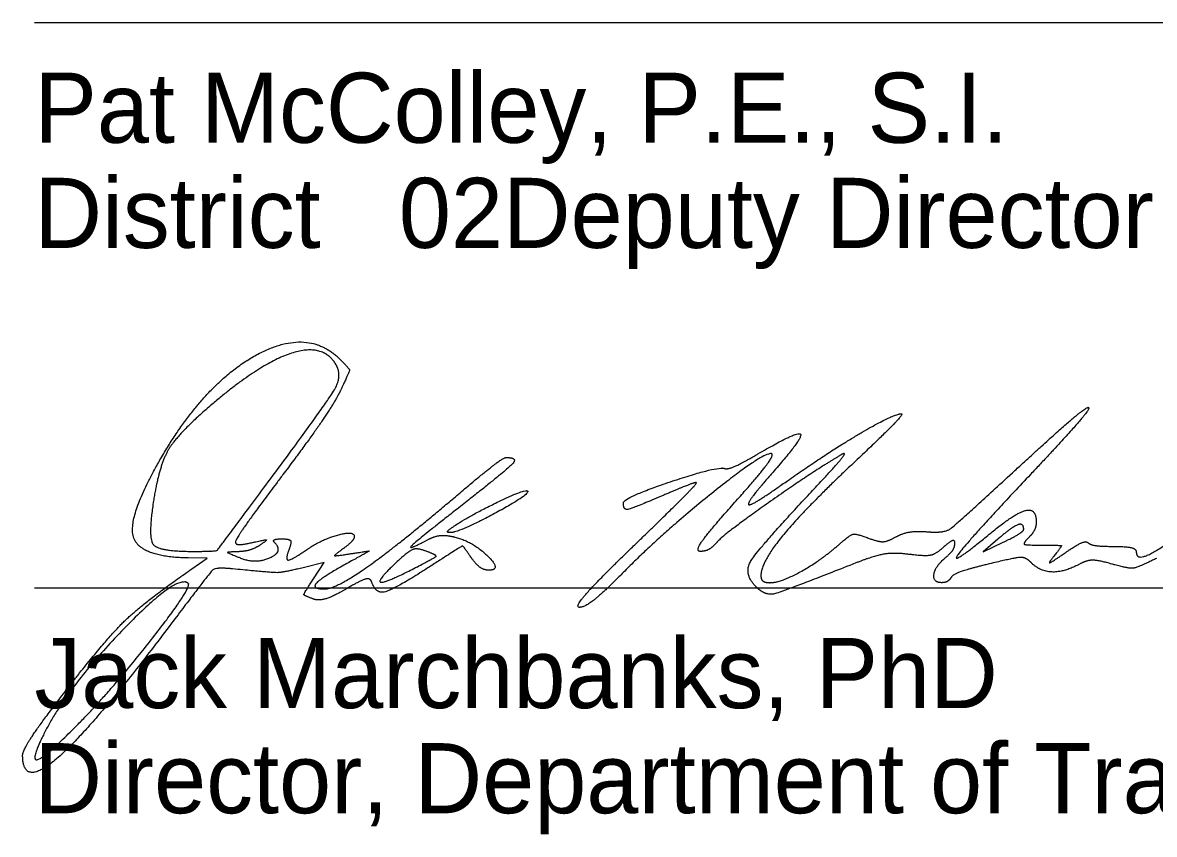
# Model space of a CAD drawing. Extents: x 0 to 34, y 0 to 22.
# Drawn here: x 24.504 to 26.766, y 7.305 to 8.926 of the extents above; entities that cross this region are included whole.
import ezdxf

# ---------------------------------------------------------------- set-up
doc = ezdxf.new("R2010")
doc.units = 0
doc.layers.add('SH_Data', color=7, linetype='Continuous')
doc.layers.add('SH_Text', color=7, linetype='Continuous')

msp = doc.modelspace()

# ---------------------------------------------------------------- linework, layer by layer
at = {"layer": 'SH_Data'}
for p, q in [((24.5279, 8.9262), (28.0279, 8.9262)), ((24.5279, 7.7968), (28.0279, 7.7968))]:
    msp.add_line(p, q, dxfattribs=at)
at = {"layer": 'SH_Text'}
for p, q in [((24.9902, 8.0019), (24.9902, 8.0019)), ((26.5045, 7.914), (26.5045, 7.914)), ((25.3555, 7.912), (25.3555, 7.912)), ((25.3107, 7.8703), (25.3107, 7.8703)), ((25.7273, 7.883), (25.7273, 7.883))]:
    msp.add_line(p, q, dxfattribs=at)
for points in [[(26.4527, 7.8943), (26.4232, 7.8687), (26.4638, 7.8884)], [(24.8425, 7.8349), (24.8732, 7.8561), (24.8354, 7.8568)], [(25.0855, 7.8151), (25.1067, 7.8474), (25.0649, 7.8373)]]:
    msp.add_lwpolyline(points, dxfattribs=at)
for points in [[(24.7789, 8.0526), (24.8651, 8.203), (25.0732, 8.319), (25.1389, 8.2534)], [(25.1299, 8.2442), (25.104, 8.2862), (24.9779, 8.245), (24.8825, 8.1634)], [(25.1389, 8.2534), (25.1577, 8.2346), (25.1577, 8.2295), (25.1394, 8.1911)], [(24.9902, 8.0019), (25.1115, 8.1653), (25.144, 8.2215), (25.1299, 8.2442)], [(25.1394, 8.1911), (25.1284, 8.1681), (25.0767, 8.0926), (25.0245, 8.0232)], [(24.8825, 8.1634), (24.8159, 8.1064), (24.7771, 8.0423), (24.766, 7.971)], [(26.0326, 8.0111), (26.1131, 8.0677), (26.2445, 8.1449), (26.2602, 8.1449)], [(26.2602, 8.1449), (26.265, 8.1449), (26.2237, 8.1023), (26.1684, 8.0502)], [(26.4869, 8.0315), (26.5619, 8.1006), (26.6279, 8.1572), (26.6336, 8.1573)], [(26.6336, 8.1573), (26.6394, 8.1574), (26.5873, 8.0972), (26.518, 8.0236)], [(25.9736, 8.0646), (26.0524, 8.1108), (26.0646, 8.0975), (26.0054, 8.0302)], [(24.8354, 7.8568), (24.7375, 7.8585), (24.7141, 7.9396), (24.7789, 8.0526)], [(25.369, 7.9791), (25.4194, 8.022), (25.4649, 8.0571), (25.4701, 8.0573)], [(25.4701, 8.0573), (25.495, 8.0578), (25.4716, 8.0322), (25.3857, 7.9649)], [(26.0017, 8.0644), (25.9921, 8.074), (25.7824, 7.907), (25.7045, 7.8278)], [(26.142, 8.0639), (26.0929, 8.0361), (25.9046, 7.9039), (25.8914, 7.888)], [(25.908, 8.0354), (25.9136, 8.0335), (25.9431, 8.0467), (25.9736, 8.0646)], [(25.9239, 7.964), (25.9702, 8.0157), (26.0052, 8.0609), (26.0017, 8.0644)], [(26.1684, 8.0502), (26.0687, 7.9565), (25.9795, 7.8484), (25.9795, 7.8214)], [(26.0768, 7.985), (26.123, 8.0342), (26.1523, 8.0697), (26.142, 8.0639)], [(25.7047, 7.9668), (25.7049, 7.9774), (25.8923, 8.0405), (25.908, 8.0354)], [(26.0054, 8.0302), (25.9774, 7.9984), (25.9545, 7.9687), (25.9545, 7.9643)], [(26.3119, 7.9091), (26.3453, 7.9063), (26.3688, 7.9227), (26.4869, 8.0315)], [(25.0245, 8.0232), (24.9722, 7.9539), (24.9295, 7.8932), (24.9295, 7.8884)], [(25.7273, 7.883), (25.7983, 7.9514), (25.8537, 8.0074), (25.8502, 8.0074)], [(25.8502, 8.0074), (25.8468, 8.0074), (25.8178, 7.9962), (25.7857, 7.9824)], [(25.9545, 7.9643), (25.9545, 7.9598), (25.9896, 7.9809), (26.0326, 8.0111)], [(26.518, 8.0236), (26.3885, 7.8861), (26.3564, 7.8388), (26.4386, 7.9065)], [(24.844, 7.8699), (24.8907, 7.8699), (24.8953, 7.874), (24.9902, 8.0019)], [(25.3555, 7.912), (25.3759, 7.9299), (25.5079, 7.9956), (25.5131, 7.9905)], [(25.5131, 7.9905), (25.5193, 7.9843), (25.3767, 7.9074), (25.359, 7.9074)], [(25.7857, 7.9824), (25.7231, 7.9556), (25.7044, 7.952), (25.7047, 7.9668)], [(25.9697, 7.7993), (25.9445, 7.8246), (25.9734, 7.8747), (26.0768, 7.985)], [(24.766, 7.971), (24.7545, 7.8977), (24.776, 7.8699), (24.844, 7.8699)], [(25.1076, 7.7949), (25.1307, 7.7949), (25.2567, 7.8837), (25.369, 7.9791)], [(25.3857, 7.9649), (25.2925, 7.8919), (25.271, 7.8704), (25.315, 7.8939)], [(25.8581, 7.8699), (25.8478, 7.8699), (25.8767, 7.9112), (25.9239, 7.964)], [(26.7295, 7.8684), (26.7295, 7.8456), (26.8248, 7.907), (26.8951, 7.9753)], [(26.4386, 7.9065), (26.487, 7.9464), (26.5295, 7.9568), (26.5295, 7.9287)], [(26.5045, 7.914), (26.5045, 7.9275), (26.4804, 7.9183), (26.4527, 7.8943)], [(26.4638, 7.8884), (26.4862, 7.8992), (26.5045, 7.9107), (26.5045, 7.914)], [(26.5295, 7.9287), (26.5295, 7.9198), (26.5227, 7.9057), (26.5145, 7.8974)], [(24.9638, 7.8877), (24.9894, 7.8936), (24.9934, 7.8924), (24.9795, 7.883)], [(25.0086, 7.8867), (25.004, 7.8912), (25.0103, 7.8949), (25.0225, 7.8949)], [(25.0225, 7.8949), (25.037, 7.8949), (25.0422, 7.8885), (25.0375, 7.8762)], [(25.0736, 7.8743), (25.1025, 7.8941), (25.167, 7.9116), (25.167, 7.8997)], [(25.167, 7.8997), (25.167, 7.8952), (25.1572, 7.8843), (25.1453, 7.8756)], [(25.315, 7.8939), (25.3276, 7.9006), (25.3515, 7.9027), (25.3681, 7.8985)], [(25.359, 7.9074), (25.3542, 7.9074), (25.3526, 7.9095), (25.3555, 7.912)], [(25.3681, 7.8985), (25.4042, 7.8894), (25.4625, 7.8324), (25.4358, 7.8324)], [(26.137, 7.885), (26.1573, 7.903), (26.1701, 7.9056), (26.1939, 7.8966)], [(26.1939, 7.8966), (26.2141, 7.8889), (26.2329, 7.8896), (26.2489, 7.8987)], [(26.2489, 7.8987), (26.2623, 7.9062), (26.2906, 7.9109), (26.3119, 7.9091)], [(26.367, 7.8859), (26.367, 7.893), (26.3568, 7.8896), (26.3444, 7.8784)], [(26.5145, 7.8974), (26.5028, 7.8858), (26.5087, 7.8824), (26.541, 7.8824)], [(24.9357, 7.8693), (24.9133, 7.8685), (24.9138, 7.8671), (24.9399, 7.8567)], [(24.9295, 7.8884), (24.9295, 7.8836), (24.9449, 7.8833), (24.9638, 7.8877)], [(24.9795, 7.883), (24.9692, 7.876), (24.9495, 7.8699), (24.9357, 7.8693)], [(24.9399, 7.8567), (24.9698, 7.8447), (25.026, 7.8693), (25.0086, 7.8867)], [(25.0375, 7.8762), (25.0285, 7.8529), (25.0414, 7.8523), (25.0736, 7.8743)], [(25.1453, 7.8756), (25.1264, 7.8618), (25.1284, 7.8605), (25.161, 7.8654)], [(25.161, 7.8654), (25.1977, 7.871), (25.1976, 7.8707), (25.1522, 7.8456)], [(25.3107, 7.8703), (25.2935, 7.8767), (25.277, 7.8716), (25.2576, 7.8538)], [(25.2826, 7.834), (25.329, 7.8577), (25.3325, 7.8623), (25.3107, 7.8703)], [(25.4011, 7.8571), (25.3843, 7.8812), (25.3822, 7.8807), (25.3165, 7.8384)], [(25.617, 7.7581), (25.6067, 7.7583), (25.6563, 7.8145), (25.7273, 7.883)], [(25.8914, 7.888), (25.8831, 7.878), (25.8682, 7.8699), (25.8581, 7.8699)], [(25.9975, 7.8074), (26.0192, 7.8074), (26.1006, 7.8527), (26.137, 7.885)], [(26.3444, 7.8784), (26.3287, 7.8642), (26.3075, 7.8598), (26.2749, 7.864)], [(26.3482, 7.8574), (26.3585, 7.866), (26.367, 7.8788), (26.367, 7.8859)], [(26.541, 7.8824), (26.5785, 7.8824), (26.5809, 7.8804), (26.5654, 7.8611)], [(26.5871, 7.8669), (26.6085, 7.8819), (26.6293, 7.891), (26.6332, 7.8871)], [(26.6332, 7.8871), (26.6371, 7.8831), (26.6604, 7.8799), (26.6849, 7.8799)], [(26.6849, 7.8799), (26.7094, 7.8799), (26.7295, 7.8748), (26.7295, 7.8684)], [(25.2576, 7.8538), (25.2133, 7.8133), (25.2246, 7.8044), (25.2826, 7.834)], [(25.4358, 7.8324), (25.4262, 7.8324), (25.4106, 7.8435), (25.4011, 7.8571)], [(26.1693, 7.8468), (26.0233, 7.7891), (25.9882, 7.7808), (25.9697, 7.7993)], [(26.2749, 7.864), (26.2457, 7.8677), (26.2058, 7.8612), (26.1693, 7.8468)], [(26.3412, 7.8074), (26.3229, 7.8074), (26.3274, 7.8402), (26.3482, 7.8574)], [(26.5199, 7.847), (26.5088, 7.8582), (26.4887, 7.8577), (26.4355, 7.8449)], [(26.6162, 7.8445), (26.5854, 7.8281), (26.5376, 7.8293), (26.5199, 7.847)], [(26.5654, 7.8611), (26.5533, 7.8461), (26.5598, 7.8478), (26.5871, 7.8669)], [(26.6807, 7.8446), (26.6538, 7.8523), (26.6307, 7.8523), (26.6162, 7.8445)], [(26.7698, 7.8559), (26.7324, 7.8374), (26.7138, 7.8351), (26.6807, 7.8446)], [(24.5916, 7.5927), (24.6692, 7.6932), (24.7493, 7.7705), (24.8425, 7.8349)], [(24.9237, 7.835), (24.8903, 7.8383), (24.8786, 7.8278), (24.8019, 7.7262)], [(25.0649, 7.8373), (25.0246, 7.8276), (25.0023, 7.8272), (24.9237, 7.835)], [(25.1522, 7.8456), (25.1011, 7.8174), (25.0814, 7.7949), (25.1076, 7.7949)], [(25.3165, 7.8384), (25.2476, 7.794), (25.2101, 7.7843), (25.202, 7.8086)], [(25.7045, 7.8278), (25.6667, 7.7893), (25.6273, 7.7579), (25.617, 7.7581)], [(26.4355, 7.8449), (26.3972, 7.8357), (26.3629, 7.8235), (26.3594, 7.8178)], [(24.8354, 7.8057), (24.8145, 7.8266), (24.596, 7.6009), (24.5497, 7.5106)], [(24.6198, 7.5293), (24.6874, 7.5984), (24.8431, 7.798), (24.8354, 7.8057)], [(25.0843, 7.775), (25.0661, 7.782), (25.0662, 7.7856), (25.0855, 7.8151)], [(25.202, 7.8086), (25.1991, 7.8172), (25.1799, 7.812), (25.1508, 7.7948)], [(25.9795, 7.8214), (25.9795, 7.8137), (25.9876, 7.8074), (25.9975, 7.8074)], [(26.3594, 7.8178), (26.3559, 7.8121), (26.3477, 7.8074), (26.3412, 7.8074)], [(25.1508, 7.7948), (25.1252, 7.7797), (25.0953, 7.7708), (25.0843, 7.775)], [(24.8019, 7.7262), (24.6496, 7.5241), (24.5045, 7.3955), (24.5045, 7.4625)], [(24.5045, 7.4625), (24.5045, 7.4721), (24.5437, 7.5307), (24.5916, 7.5927)], [(24.5497, 7.5106), (24.5184, 7.4496), (24.55, 7.4581), (24.6198, 7.5293)]]:
    msp.add_open_spline(points, degree=2, dxfattribs=at)

# ---------------------------------------------------------------- texts
for s, p in [('Pat McColley, P.E., S.I.', (24.5279, 8.6862)), ('District       Deputy Director', (24.5279, 8.4762)), ('              02', (24.5279, 8.4762)), ('Jack Marchbanks, PhD', (24.5279, 7.5568)), ('Director, Department of Transportation', (24.5279, 7.3468))]:
    msp.add_text(s, height=0.14, dxfattribs=at).set_placement(p)

doc.saveas('drawing.dxf')
